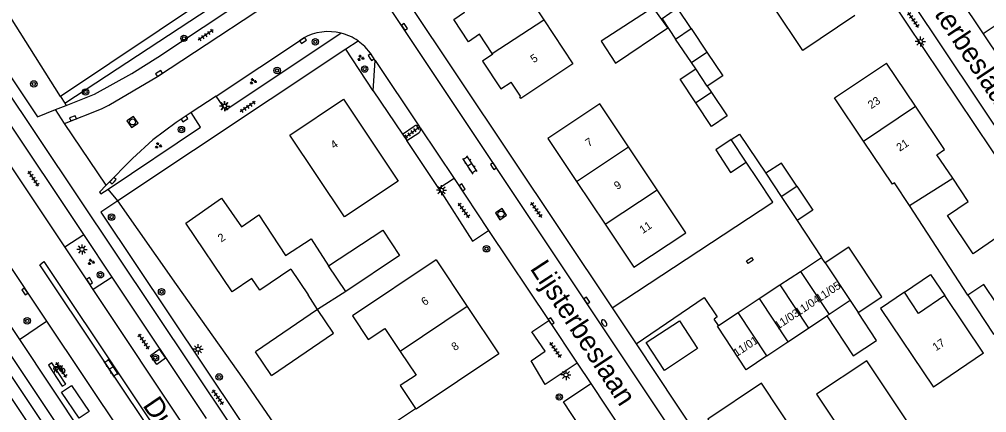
# Model space of a CAD drawing. Extents: x 137999 to 141000, y 397500 to 400501.
# Drawn here: x 138413.7 to 138533.8, y 399653.3 to 399702.2 of the extents above; entities that cross this region are included whole.
import ezdxf

# ---------------------------------------------------------------- set-up
doc = ezdxf.new("R2010")
doc.units = 0
for name, color, linetype in [('gg-afsc-erfafscheiding', 7, 'Continuous'), ('gg-afsc-muur', 7, 'Continuous'), ('gg-anno-huisnummerreeks BGT', 7, 'Continuous'), ('gg-anno-openbare ruimte label', 7, 'Continuous'), ('gg-bbg-abri', 7, 'Continuous'), ('gg-bbg-bijgebouw', 7, 'Continuous'), ('gg-bbg-gedigitaliseerde bebouwing', 7, 'Continuous'), ('gg-bbg-gedigitaliseerde bijgebouw', 7, 'Continuous'), ('gg-bbg-hoofdgebouw', 7, 'Continuous'), ('gg-bbg-luifel en loopbrug', 7, 'Continuous'), ('gg-bbg-tussenscheiding', 7, 'Continuous'), ('gg-knt-verharding', 7, 'Continuous'), ('gg-knt-verharding nz', 7, 'Continuous'), ('gt-grn-groengrens', 7, 'Continuous'), ('gt-grn-weggrens', 7, 'Continuous'), ('gt-symb-boom', 7, 'Continuous'), ('gt-symb-brandkraan', 7, 'Continuous'), ('gt-symb-fietsenrek', 7, 'Continuous'), ('gt-symb-groenvak', 7, 'Continuous'), ('gt-symb-klinker verharding', 7, 'Continuous'), ('gt-symb-kolk', 7, 'Continuous'), ('gt-symb-kolk center center', 7, 'Continuous'), ('gt-symb-lichtmast', 7, 'Continuous'), ('gt-symb-rioolschacht', 7, 'Continuous'), ('gt-symb-tegel verharding', 7, 'Continuous')]:
    doc.layers.add(name, color=color, linetype=linetype)

# ---------------------------------------------------------------- blocks, each defined once
blk = doc.blocks.new('gt0-BOOM')
at = {"layer": 'gt-symb-boom'}
for radius in [0.4, 0.2]:
    blk.add_circle((0, 0), radius, dxfattribs=at)
blk = doc.blocks.new('gt0-KOLK')
at = {"layer": 'gt-symb-kolk'}
blk.add_lwpolyline([(0, 0), (0.37, 0), (0.37, 0.4), (-0.38, 0.4), (-0.38, 0), (0, 0)], dxfattribs=at)
blk = doc.blocks.new('gt0-GRVAK')
at = {"layer": 'gt-symb-groenvak'}
for p, q in [((-0.11, 0.19), (-0.23, 0.24)), ((-0.18, 0.15), (0.09, 0.15)), ((-0.09, 0.21), (-0.16, 0.32)), ((-0.05, 0.21), (-0.05, 0.39)), ((0, 0.21), (0.06, 0.32)), ((0.02, 0.19), (0.13, 0.24)), ((0.26, -0.05), (0.2, 0.06)), ((0.31, -0.05), (0.31, 0.13)), ((0.35, -0.05), (0.41, 0.06)), ((-0.24, -0.23), (-0.36, -0.18)), ((-0.32, -0.26), (-0.05, -0.26)), ((-0.23, -0.21), (-0.29, -0.09)), ((-0.18, -0.2), (-0.18, -0.02)), ((-0.14, -0.21), (-0.07, -0.09)), ((-0.12, -0.23), (0, -0.18)), ((0.24, -0.07), (0.12, -0.02)), ((0.17, -0.11), (0.44, -0.11)), ((0.37, -0.07), (0.49, -0.02))]:
    blk.add_line(p, q, dxfattribs=at)
blk = doc.blocks.new('gt0-KL1')
at = {"layer": 'gt-symb-klinker verharding'}
for p, q in [((-1.15, 0.3), (1.15, 0.3)), ((-1, -0.3), (-1, 0.3)), ((-0.5, 0.3), (-0.5, 0.45)), ((0, -0.3), (0, 0.3)), ((0.5, 0.3), (0.5, 0.45)), ((1, -0.3), (1, 0.3)), ((-1.15, -0.3), (1.15, -0.3)), ((-0.5, -0.45), (-0.5, -0.3)), ((0.5, -0.45), (0.5, -0.3))]:
    blk.add_line(p, q, dxfattribs=at)
blk = doc.blocks.new('gt0-TEG1')
at = {"layer": 'gt-symb-tegel verharding'}
for p, q in [((-1.13, 0), (1.12, 0)), ((-0.9, -0.25), (-0.9, 0.25)), ((-0.45, -0.25), (-0.45, 0.25)), ((0, -0.25), (0, 0.25)), ((0.45, -0.25), (0.45, 0.25)), ((0.9, -0.25), (0.9, 0.25))]:
    blk.add_line(p, q, dxfattribs=at)
blk = doc.blocks.new('gt0-RS')
at = {"layer": 'gt-symb-rioolschacht'}
blk.add_lwpolyline([(-0.5, -0.5), (0.5, -0.5), (0.5, 0.5), (-0.5, 0.5)], close=True, dxfattribs=at)
blk.add_circle((0, 0), 0.375, dxfattribs=at)
blk = doc.blocks.new('gt0-LMAST')
at = {"layer": 'gt-symb-lichtmast'}
for p, q in [((-0.18, 0.17), (-0.45, 0.44)), ((0, 0.25), (0, 0.62)), ((0.17, 0.17), (0.44, 0.44)), ((-0.25, 0), (-0.63, 0)), ((-0.18, -0.18), (-0.45, -0.45)), ((0, -0.25), (0, -0.63)), ((0.44, -0.45), (0.17, -0.18)), ((0.25, 0), (0.62, 0))]:
    blk.add_line(p, q, dxfattribs=at)
blk.add_circle((0, 0), 0.25, dxfattribs=at)
blk = doc.blocks.new('gt0-BR')
at = {"layer": 'gt-symb-brandkraan'}
for centre, radius, start, end in [((-0.24, 0), 0.206, 107.5669, 252.4331), ((0.6, -2.66), 3, 106.892, 107.5669), ((0, -0.69), 0.938, 73.108, 106.892), ((-0.6, -2.66), 3, 72.4331, 73.108), ((0.24, 0), 0.206, 287.567, 72.4331), ((0.6, 2.66), 3, 252.4331, 253.108), ((0, 0.69), 0.938, 253.108, 286.8921), ((-0.6, 2.66), 3, 286.8921, 287.567)]:
    blk.add_arc(centre, radius, start, end, dxfattribs=at)
blk = doc.blocks.new('gt0-KOLKCC')
at = {"layer": 'gt-symb-kolk center center'}
blk.add_lwpolyline([(-0.38, 0.2), (0.37, 0.2), (0.37, -0.2), (-0.38, -0.2)], close=True, dxfattribs=at)
blk = doc.blocks.new('gt0-FREK')
at = {"layer": 'gt-symb-fietsenrek'}
for p, q in [((0.26, 0.76), (0.29, 0.82)), ((0.54, 0.34), (0.26, 0.76)), ((0.29, 0.82), (0.77, 0.71)), ((0.77, 0.71), (0.54, 0.34)), ((0.76, 0.84), (0.87, 0.82)), ((0.77, 0.71), (0.84, 0.82)), ((0.89, 0.25), (0.77, 0.71))]:
    blk.add_line(p, q, dxfattribs=at)
for points in [[(-0.12, 0), (-0.05, 0.31), (0.05, 0.31), (0.12, 0)], [(0.04, 0.48), (0.23, 0.71), (0.26, 0.76)], [(0.29, 0.82), (0.36, 0.94), (0.45, 0.93)], [(0.54, 0.34), (0.56, 0.31), (0.89, 0.25)]]:
    blk.add_lwpolyline(points, dxfattribs=at)
for centre in [(0.04, 0.48), (0.89, 0.25)]:
    blk.add_circle(centre, 0.252, dxfattribs=at)

msp = doc.modelspace()

# ---------------------------------------------------------------- linework, layer by layer
at = {"layer": 'gg-afsc-erfafscheiding'}
for p, q in [((138517.84, 399723.55), (138533.35, 399700.35)), ((138446.98, 399711.46), (138418.83, 399692.58)), ((138457.64, 399693.27), (138454.25, 399698.46)), ((138505.39, 399682.3), (138503.94, 399684.45)), ((138510.27, 399677.2), (138513.3, 399672.61)), ((138500.5, 399664.16), (138499.95, 399664.96))]:
    msp.add_line(p, q, dxfattribs=at)
for points in [[(138418.83, 399692.58), (138390.34, 399737.73), (138386.53, 399743.42), (138388.04, 399744.84)], [(138502.09, 399687.23), (138503.09, 399687.9), (138506.37, 399683.05)], [(138449.72, 399645.57), (138441.57, 399657.48), (138433.23, 399669.24), (138425.95, 399679.64)]]:
    msp.add_lwpolyline(points, dxfattribs=at)
at = {"layer": 'gg-afsc-muur'}
msp.add_line((138460.4, 399652.19), (138462.9, 399653.86), dxfattribs=at)
at = {"layer": 'gg-bbg-abri'}
msp.add_lwpolyline([(138418.96, 399655.89), (138420.2, 399656.72), (138422.38, 399653.48), (138421.15, 399652.65), (138418.96, 399655.89)], dxfattribs=at)
at = {"layer": 'gg-bbg-bijgebouw'}
for p, q in [((138506.37, 399683.05), (138508.29, 399680.17)), ((138508.29, 399680.17), (138510.27, 399677.2)), ((138510.66, 399670.87), (138513.3, 399672.61)), ((138508.13, 399669.2), (138510.66, 399670.87)), ((138505.56, 399667.5), (138508.13, 399669.2)), ((138502.95, 399665.77), (138505.56, 399667.5)), ((138500.5, 399664.16), (138502.95, 399665.77)), ((138445.03, 399657.96), (138443.03, 399660.89))]:
    msp.add_line(p, q, dxfattribs=at)
for points in [[(138510.21, 399681.46), (138508.3, 399684.33), (138506.37, 399683.05)], [(138510.21, 399681.46), (138512.21, 399678.48), (138510.27, 399677.2)], [(138452.1, 399671.57), (138458.82, 399676.01), (138460.92, 399672.87), (138454.24, 399668.4)], [(138503.93, 399658.68), (138500.37, 399664.07), (138500.5, 399664.16)]]:
    msp.add_lwpolyline(points, dxfattribs=at)
at = {"layer": 'gg-bbg-gedigitaliseerde bebouwing'}
for p, q in [((138475.31, 399707.36), (138478.8, 399702.1)), ((138492.87, 399681.02), (138489.32, 399686.35)), ((138524.19, 399679.06), (138522.36, 399681.86)), ((138496.43, 399675.68), (138492.87, 399681.02)), ((138531.46, 399667.93), (138524.19, 399679.06)), ((138447.43, 399671.17), (138449.57, 399667.99)), ((138454.24, 399668.4), (138450.72, 399666.14)), ((138450.72, 399666.14), (138449.57, 399667.99)), ((138533.4, 399660.72), (138528.58, 399667.87)), ((138460.99, 399656.71), (138462.9, 399653.86))]:
    msp.add_line(p, q, dxfattribs=at)
for points in [[(138517.41, 399702.62), (138510.96, 399698.31), (138507.37, 399703.67)], [(138478.8, 399702.1), (138482.43, 399696.63), (138475.98, 399692.34)], [(138518.51, 399687.06), (138514.91, 399692.41), (138521.36, 399696.73)], [(138489.32, 399686.35), (138485.77, 399691.67), (138479.32, 399687.38)], [(138522.36, 399681.86), (138522.11, 399681.7), (138518.51, 399687.06)], [(138465.46, 399672.3), (138455.08, 399665.35), (138457.03, 399662.43), (138459.08, 399663.8), (138461, 399660.93)], [(138523.57, 399668.29), (138520.61, 399666.29), (138527.18, 399656.52)], [(138528.58, 399667.87), (138525.33, 399665.67), (138523.57, 399668.29)], [(138461, 399660.93), (138462.95, 399658.01), (138460.99, 399656.71)], [(138525.54, 399649.85), (138518.92, 399659.79), (138512.68, 399655.64), (138519.3, 399645.7)]]:
    msp.add_lwpolyline(points, dxfattribs=at)
at = {"layer": 'gg-bbg-gedigitaliseerde bijgebouw'}
for p, q in [((138497.11, 399701.02), (138499.07, 399698.09)), ((138497.14, 399696.8), (138495.18, 399699.72)), ((138497.67, 399696.01), (138497.14, 399696.8)), ((138499.1, 399693.87), (138499.62, 399693.09)), ((138503.94, 399684.45), (138502.09, 399687.23)), ((138513.74, 399671.95), (138513.3, 399672.61)), ((138450.72, 399666.14), (138443.03, 399660.89)), ((138511.66, 399663.84), (138513.95, 399665.35)), ((138509.11, 399662.14), (138511.66, 399663.84)), ((138506.5, 399660.42), (138509.11, 399662.14)), ((138506.5, 399660.42), (138503.93, 399658.68))]:
    msp.add_line(p, q, dxfattribs=at)
for points in [[(138485.95, 399699.44), (138487.73, 399696.71), (138494.22, 399701.11), (138492.41, 399703.64), (138485.95, 399699.44)], [(138497.11, 399701.02), (138495.43, 399703.54), (138493.5, 399702.24), (138495.18, 399699.72)], [(138499.07, 399698.09), (138501.03, 399695.16), (138499.1, 399693.87)], [(138497.69, 399691.8), (138495.74, 399694.72), (138497.67, 399696.01)], [(138499.62, 399693.09), (138501.57, 399690.17), (138499.64, 399688.88), (138497.69, 399691.8)], [(138502.09, 399687.23), (138500.16, 399685.95), (138502.01, 399683.17), (138503.94, 399684.45)], [(138517.83, 399665.78), (138520.76, 399667.72), (138516.67, 399673.89), (138513.74, 399671.95)], [(138445.03, 399657.96), (138452.72, 399663.21), (138450.72, 399666.14)], [(138513.95, 399665.35), (138517.23, 399660.39), (138520.12, 399662.31), (138517.83, 399665.78)]]:
    msp.add_lwpolyline(points, dxfattribs=at)
at = {"layer": 'gg-bbg-hoofdgebouw'}
for p, q in [((138524.94, 399691.39), (138521.36, 399696.73)), ((138479.32, 399687.38), (138482.87, 399682.05)), ((138482.87, 399682.05), (138486.42, 399676.73)), ((138486.42, 399676.73), (138489.97, 399671.4)), ((138489.97, 399671.4), (138496.43, 399675.68)), ((138465.46, 399672.3), (138469.32, 399666.52)), ((138469.32, 399666.52), (138473.25, 399660.65)), ((138533.4, 399660.72), (138527.18, 399656.52))]:
    msp.add_line(p, q, dxfattribs=at)
for points in [[(138472.41, 399697.92), (138470.83, 399700.3), (138469.47, 399699.38), (138467.63, 399702.13), (138468.99, 399703.05), (138468.96, 399703.09)], [(138472.41, 399697.92), (138472.48, 399697.83), (138471.21, 399696.98), (138473.49, 399693.52), (138474.77, 399694.37)], [(138475.98, 399692.34), (138475.83, 399692.56), (138475.92, 399692.64), (138474.77, 399694.37)], [(138460.72, 399682.09), (138454.06, 399677.64), (138447.29, 399687.79), (138453.94, 399692.24), (138460.72, 399682.09)], [(138529.58, 399682.43), (138527.62, 399685.35), (138528.57, 399685.99), (138524.94, 399691.39)], [(138537.57, 399676.82), (138532.11, 399673.07), (138528.93, 399677.81), (138531.51, 399679.54), (138529.58, 399682.43)], [(138447.43, 399671.17), (138443.55, 399668.56), (138442.58, 399670), (138440.11, 399668.34), (138434.38, 399676.88), (138438.81, 399679.97), (138441.3, 399676.4), (138443.45, 399677.9)], [(138443.45, 399677.9), (138446.75, 399672.84), (138449.92, 399674.91), (138452.1, 399671.57)], [(138536.68, 399664.45), (138533.44, 399669.26), (138531.46, 399667.93)], [(138473.25, 399660.65), (138462.96, 399653.77), (138462.9, 399653.86)], [(138505.85, 399656.99), (138499.16, 399652.55), (138501.52, 399649.01), (138501.93, 399649.28), (138506.5, 399642.43), (138512.75, 399646.57), (138505.85, 399656.99)]]:
    msp.add_lwpolyline(points, dxfattribs=at)
at = {"layer": 'gg-bbg-luifel en loopbrug'}
for points in [[(138523.57, 399668.29), (138526.82, 399670.48), (138528.58, 399667.87)], [(138531.46, 399667.93), (138534.62, 399663.07), (138536.68, 399664.45)], [(138491.53, 399662.04), (138495.65, 399664.73), (138497.91, 399661.29), (138493.79, 399658.59), (138491.53, 399662.04)]]:
    msp.add_lwpolyline(points, dxfattribs=at)
at = {"layer": 'gg-bbg-tussenscheiding'}
for p, q in [((138472.41, 399697.92), (138478.8, 399702.1)), ((138495.18, 399699.72), (138497.11, 399701.02)), ((138497.14, 399696.8), (138499.07, 399698.09)), ((138499.1, 399693.87), (138497.67, 399696.01)), ((138499.62, 399693.09), (138497.69, 399691.8)), ((138518.51, 399687.06), (138524.94, 399691.39)), ((138482.87, 399682.05), (138489.32, 399686.35)), ((138508.29, 399680.17), (138510.21, 399681.46)), ((138524.19, 399679.06), (138529.58, 399682.43)), ((138486.42, 399676.73), (138492.87, 399681.02)), ((138513.74, 399671.95), (138516.86, 399667.27)), ((138454.24, 399668.4), (138452.1, 399671.57)), ((138510.66, 399670.87), (138514.22, 399665.54)), ((138508.13, 399669.2), (138511.66, 399663.84)), ((138505.56, 399667.5), (138509.11, 399662.14)), ((138516.86, 399667.27), (138514.22, 399665.54)), ((138516.86, 399667.27), (138517.83, 399665.78)), ((138469.32, 399666.52), (138461, 399660.93)), ((138506.5, 399660.42), (138502.95, 399665.77)), ((138514.22, 399665.54), (138513.95, 399665.35))]:
    msp.add_line(p, q, dxfattribs=at)
at = {"layer": 'gg-knt-verharding'}
for p, q in [((138548.65, 399664.68), (138508.2, 399725.15)), ((138461.83, 399704.51), (138487.29, 399666.35)), ((138506.49, 399633.45), (138459.5, 399703.87)), ((138534.74, 399701.28), (138533.35, 399700.35)), ((138438.15, 399692.64), (138448.97, 399699.81)), ((138455.77, 399699.47), (138454.25, 399698.46)), ((138533.35, 399700.35), (138535.53, 399697.11)), ((138454.25, 399698.46), (138425.95, 399679.64)), ((138457.64, 399693.27), (138457.89, 399697.07)), ((138438.15, 399692.64), (138435.03, 399690.58)), ((138457.64, 399693.27), (138461.26, 399687.91)), ((138418.21, 399690.96), (138419.52, 399691.48)), ((138421.72, 399675.45), (138411.58, 399690.63)), ((138419.37, 399673.94), (138409.27, 399689.02)), ((138424.48, 399681.56), (138419.32, 399689.25)), ((138461.26, 399687.91), (138462.73, 399688.91)), ((138463.48, 399688.69), (138463.38, 399688.84)), ((138461.26, 399687.91), (138461.81, 399687.11)), ((138461.81, 399687.11), (138463.3, 399688.08)), ((138465.79, 399681.16), (138461.81, 399687.11)), ((138467.67, 399682.41), (138465.79, 399681.16)), ((138467.67, 399682.41), (138471.96, 399675.97)), ((138419.37, 399673.94), (138421.72, 399675.45)), ((138425.25, 399670.16), (138421.72, 399675.45)), ((138471.96, 399675.97), (138479.42, 399664.8)), ((138411.66, 399672.87), (138417.1, 399664.72)), ((138408.29, 399670.55), (138413.71, 399662.43)), ((138425.25, 399670.16), (138422.88, 399668.62)), ((138436.96, 399652.63), (138425.25, 399670.16)), ((138434.6, 399651.06), (138422.88, 399668.62)), ((138487.29, 399666.35), (138490.28, 399661.87)), ((138413.71, 399662.43), (138417.1, 399664.72)), ((138417.1, 399664.72), (138428.82, 399647.17)), ((138479.42, 399664.8), (138482.95, 399659.51)), ((138413.71, 399662.43), (138425.42, 399644.92)), ((138490.28, 399661.87), (138498.34, 399649.78)), ((138482.95, 399659.51), (138484.65, 399656.97))]:
    msp.add_line(p, q, dxfattribs=at)
for points in [[(138549.08, 399667.63), (138512.12, 399722.92), (138511.49, 399724.21), (138510.9, 399726.94)], [(138419.52, 399691.48), (138423.03, 399692.89), (138427.67, 399695.42), (138430.91, 399697.47), (138447.77, 399708.69)], [(138419.32, 399689.25), (138423.92, 399691.06), (138424.8, 399691.49), (138430.87, 399695.06), (138449.1, 399707.12)], [(138453.65, 399700.44), (138439.35, 399690.88), (138438.15, 399692.64)], [(138457.89, 399697.07), (138457.29, 399697.96), (138456.59, 399698.78), (138455.77, 399699.47)], [(138449.48, 399637.57), (138411.51, 399694.35), (138410.48, 399695.89)], [(138411.56, 399696.63), (138415.95, 399690.05), (138418.21, 399690.96)], [(138435.03, 399690.58), (138433.18, 399689.35), (138430.3, 399687.2), (138427.77, 399684.89), (138424.48, 399681.56)], [(138424.72, 399681.1), (138436.21, 399688.78), (138435.03, 399690.58)], [(138440.32, 399619.02), (138406.23, 399670.04), (138395.71, 399685.81)], [(138424.48, 399681.56), (138423.66, 399680.72), (138423.81, 399680.49), (138424.72, 399681.1)], [(138487.29, 399666.35), (138507.23, 399679.47), (138505.39, 399682.3)], [(138465.79, 399681.16), (138469.96, 399674.61), (138471.96, 399675.97)], [(138425.95, 399679.64), (138423.83, 399678.23), (138449.56, 399639.76), (138452.55, 399635.69)], [(138422.88, 399668.62), (138422.27, 399669.57), (138419.37, 399673.94)], [(138416.26, 399671.7), (138416.76, 399672.09), (138447.33, 399626.33), (138446.81, 399625.97), (138416.26, 399671.7)], [(138403.83, 399668.45), (138405.06, 399669.31), (138439.83, 399617.24), (138438.86, 399616.6), (138440.18, 399614.57)], [(138490.28, 399661.87), (138498.71, 399667.65), (138500.34, 399665.22), (138499.95, 399664.96)], [(138482.95, 399659.51), (138479, 399656.83), (138477.24, 399659.79), (138478.99, 399660.97), (138477.34, 399663.39), (138479.42, 399664.8)], [(138431.08, 399661.22), (138431.85, 399660.1), (138430.76, 399659.34), (138429.98, 399660.45), (138431.08, 399661.22)], [(138488.64, 399650.98), (138485.23, 399648.66), (138481.25, 399654.68), (138484.65, 399656.97)]]:
    msp.add_lwpolyline(points, dxfattribs=at)
for centre, radius, start, end in [((138452.1, 399694.26), 6.38, 75.9145, 119.3742), ((138452.09, 399694.24), 6.4, 54.9029, 75.8835), ((138463.01, 399688.49), 0.506, 44.4727, 123.8063), ((138463.02, 399688.49), 0.503, 304.8745, 23.1604)]:
    msp.add_arc(centre, radius, start, end, dxfattribs=at)
at = {"layer": 'gg-knt-verharding nz'}
for p, q in [((138457.89, 399697.07), (138463.38, 399688.84)), ((138463.48, 399688.69), (138467.67, 399682.41)), ((138484.65, 399656.97), (138488.64, 399650.98))]:
    msp.add_line(p, q, dxfattribs=at)
msp.add_lwpolyline([(138417.31, 399659.26), (138419.04, 399656.62), (138419.5, 399656.9), (138417.74, 399659.53), (138417.31, 399659.26)], dxfattribs=at)
at = {"layer": 'gt-grn-groengrens'}
for p, q in [((138418.83, 399692.58), (138419.36, 399691.74)), ((138419.36, 399691.74), (138419.52, 399691.48))]:
    msp.add_line(p, q, dxfattribs=at)
for points in [[(138419.36, 399691.74), (138447.76, 399710.41), (138446.98, 399711.46)], [(138439.33, 399614), (138436.2, 399618.62), (138436.83, 399619.04), (138403.83, 399668.45)]]:
    msp.add_lwpolyline(points, dxfattribs=at)
at = {"layer": 'gt-grn-weggrens'}
for p, q in [((138419.32, 399689.25), (138418.21, 399690.96)), ((138425.95, 399679.64), (138424.72, 399681.1))]:
    msp.add_line(p, q, dxfattribs=at)

# ---------------------------------------------------------------- block references
at = {"layer": 'gt-symb-boom'}
for p in [(138434.15, 399699.8), (138450.45, 399699.37), (138445.71, 399695.81), (138456.58, 399695.99), (138433.83, 399688.48), (138425.16, 399677.62), (138471.7, 399673.69), (138423.77, 399670.46), (138431.37, 399668.34), (138414.69, 399664.74), (138430.6, 399660.16), (138438.52, 399657.78), (138480.74, 399655.29)]:
    msp.add_blockref('gt0-BOOM', p, dxfattribs=at)
for p, rotation in [((138415.51, 399694.14), 123.78542795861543), ((138421.93, 399693.14), 123.78542795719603)]:
    msp.add_blockref('gt0-BOOM', p, dxfattribs=dict(at, rotation=rotation))
at = {"layer": 'gt-symb-brandkraan', "rotation": -56.50059992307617}
msp.add_blockref('gt0-BR', (138486.31, 399664.48), dxfattribs=at)
at = {"layer": 'gt-symb-fietsenrek'}
msp.add_blockref('gt0-FREK', (138418.2, 399658.35), dxfattribs=at)
at = {"layer": 'gt-symb-groenvak'}
for p in [(138456.07, 399697.37), (138442.72, 399694.47), (138430.95, 399686.5), (138422.61, 399672.04)]:
    msp.add_blockref('gt0-GRVAK', p, dxfattribs=at)
at = {"layer": 'gt-symb-klinker verharding', "rotation": 123.49940007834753}
for p in [(138469.65, 399684.09), (138425.12, 399658.89)]:
    msp.add_blockref('gt0-KL1', p, dxfattribs=at)
at = {"layer": 'gt-symb-kolk'}
for p, rotation in [((138461.34, 399701.11), -56.2940434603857), ((138449.04, 399699.38), 33.49940007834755), ((138457.22, 399697.34), -56.29404346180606), ((138431.17, 399695.26), 33.49940007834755), ((138420.45, 399689.69), 21.461063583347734), ((138434.33, 399689.63), 33.49940007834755), ((138472.41, 399683.82), -56.29404346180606), ((138425.48, 399682), 45.405196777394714), ((138468.5, 399681.19), -56.29404346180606), ((138422.27, 399669.57), -57.04099012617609), ((138414.57, 399668.49), 123.65827186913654), ((138484.01, 399667.15), -56.29404346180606), ((138479.57, 399664.58), -56.29404346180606)]:
    msp.add_blockref('gt0-KOLK', p, dxfattribs=dict(at, rotation=rotation))
at = {"layer": 'gt-symb-kolk center center', "rotation": -146.1350568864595}
msp.add_blockref('gt0-KOLKCC', (138504.38, 399672.24), dxfattribs=at)
at = {"layer": 'gt-symb-lichtmast'}
for p in [(138525.56, 399699.4), (138439.17, 399691.39), (138439.21, 399691.39), (138466.11, 399680.95), (138421.49, 399673.61), (138435.9, 399661.21), (138481.57, 399658.03)]:
    msp.add_blockref('gt0-LMAST', p, dxfattribs=at)
at = {"layer": 'gt-symb-rioolschacht'}
for p, rotation in [((138427.76, 399689.43), 33.49940007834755), ((138473.5, 399677.99), -56.294043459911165)]:
    msp.add_blockref('gt0-RS', p, dxfattribs=dict(at, rotation=rotation))
at = {"layer": 'gt-symb-tegel verharding'}
for p, rotation in [((138524.69, 399702.09), 125.23135738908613), ((138436.83, 399700.21), -145.5150919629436), ((138442.06, 399691.31), -145.5150919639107), ((138462.48, 399688.15), 36.5834211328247), ((138415.48, 399682.38), 123.78542795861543), ((138468.89, 399678.43), 125.23135738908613), ((138477.9, 399678.51), 125.23135738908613), ((138429.15, 399662.16), 124.03952455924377), ((138480.27, 399661.12), 125.23135739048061), ((138418.92, 399658.66), 124.03952455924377), ((138438.34, 399655.27), -54.52896067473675)]:
    msp.add_blockref('gt0-TEG1', p, dxfattribs=dict(at, rotation=rotation))

# ---------------------------------------------------------------- texts
at = {"layer": 'gg-anno-huisnummerreeks BGT'}
for s, rotation, p in [('5', 33.6, (138477.56, 399696.7)), ('23', 33.9, (138519.46, 399691)), ('7', 33.7, (138484.39, 399686.29)), ('4', 33.8, (138452.75, 399686.03)), ('21', 33.9, (138523, 399685.72)), ('9', 33.7, (138487.94, 399680.96)), ('11', 33.7, (138491.1, 399675.51)), ('2', 34.9, (138438.78, 399674.46)), ('11/05', 33.6, (138513, 399667.02)), ('6', 33.8, (138464.01, 399666.57)), ('11/04', 33.5, (138510.42, 399665.31)), ('11/03', 33.5, (138507.87, 399663.63)), ('11/01', 33.5, (138502.75, 399660.24)), ('17', 34, (138527.49, 399660.95)), ('8', 33.8, (138467.76, 399660.97))]:
    msp.add_text(s, height=1, rotation=rotation, dxfattribs=at).set_placement(p)
at = {"layer": 'gg-anno-openbare ruimte label'}
for s, rotation, p in [('Lijsterbeslaan', 303.7, (138524.44, 399706.99)), ('Lijsterbeslaan', 303.2, (138477.04, 399671.23)), ('Durendaelweg', 304, (138428.95, 399654.25))]:
    msp.add_text(s, height=2.5, rotation=rotation, dxfattribs=at).set_placement(p)

doc.saveas('drawing.dxf')
